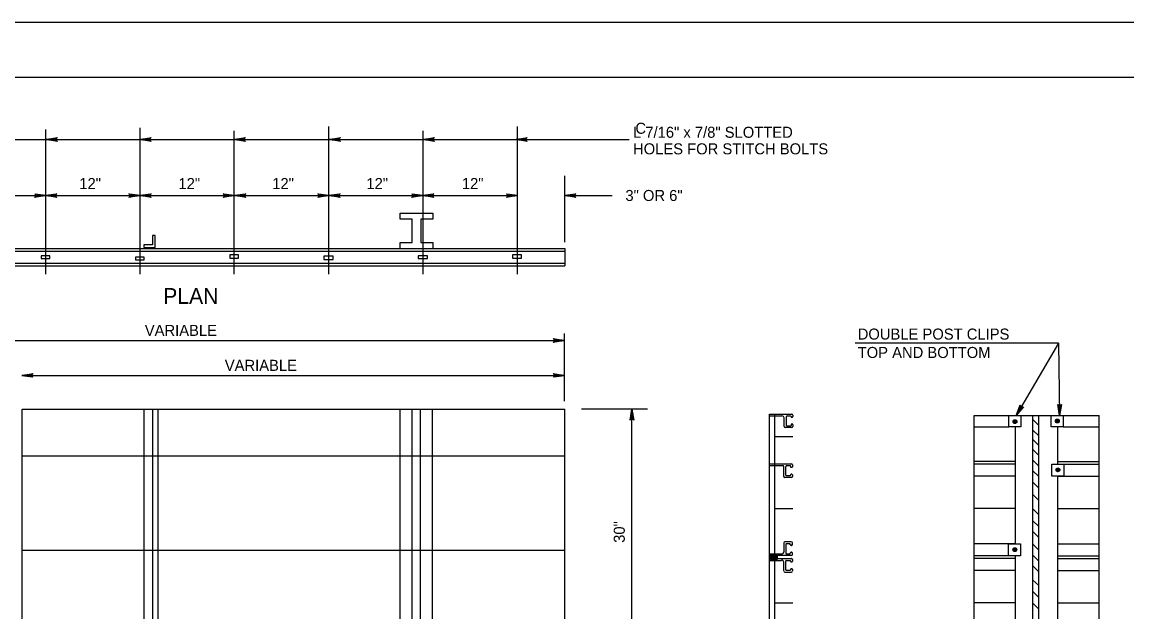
# Model space of a CAD drawing. Extents: x 647822 to 649292, y 298458 to 299646.
# Drawn here: x 647981.4 to 648281.8, y 299485.4 to 299645.6 of the extents above; entities that cross this region are included whole.
import ezdxf

# ---------------------------------------------------------------- set-up
doc = ezdxf.new("R2010")
doc.units = 0
for name, color, linetype in [('1', 7, 'Continuous'), ('2', 7, 'Continuous'), ('3', 7, 'Continuous'), ('XCS-GRID-MIN', 7, 'Continuous')]:
    doc.layers.add(name, color=color, linetype=linetype)

# ---------------------------------------------------------------- blocks, each defined once
blk = doc.blocks.new('RARROW')
at = {"layer": '3'}
blk.add_lwpolyline([(-2.2695, 0.285), (-2.184875, 0.12075), (0, 0), (-2.2695, 0.285), (-2.38575, 0.384625), (0, 0), (-2.183125, -0.108), (-2.262875, -0.2705), (0, 0), (-2.38575, -0.379125), (-2.262875, -0.2705)], dxfattribs=at)

msp = doc.modelspace()

# ---------------------------------------------------------------- linework, layer by layer
at = {"layer": '1'}
msp.add_line((647862.31, 299630.63), (648648.31, 299630.63), dxfattribs=at)
at = {"layer": '2'}
for p, q in [((647987.88, 299577.1), (647987.88, 299616.48)), ((648013.5, 299577.1), (648013.5, 299616.85)), ((648039.13, 299577.1), (648039.13, 299616.1)), ((648064.88, 299577.1), (648064.88, 299617.23)), ((648090.5, 299577.1), (648090.5, 299616.1)), ((648116.13, 299577.1), (648116.13, 299617.23)), ((647962.25, 299613.73), (647987.88, 299613.73)), ((647988, 299613.73), (648013.5, 299613.73)), ((647988, 299613.73), (647988, 299613.73)), ((648013.5, 299613.73), (648039.13, 299613.73)), ((648013.5, 299613.73), (648013.5, 299613.73)), ((648039.13, 299613.73), (648064.88, 299613.73)), ((648039.13, 299613.73), (648039.13, 299613.73)), ((648065, 299613.73), (648090.5, 299613.73)), ((648065, 299613.73), (648065, 299613.73)), ((648090.5, 299613.73), (648115.75, 299613.73)), ((648090.5, 299613.73), (648090.5, 299613.73)), ((648115.75, 299613.73), (648146.5, 299613.73)), ((648115.75, 299613.73), (648115.75, 299613.73)), ((648129, 299585.85), (648129, 299603.85)), ((647962.38, 299598.48), (647987.88, 299598.48)), ((647987.88, 299598.48), (648013.5, 299598.48)), ((648013.5, 299598.48), (648039.13, 299598.48)), ((648039.25, 299598.48), (648064.88, 299598.48)), ((648064.88, 299598.48), (648090.38, 299598.48)), ((648090.38, 299598.48), (648116.13, 299598.48)), ((648129, 299598.48), (648141.88, 299598.48)), ((648084.25, 299592.1), (648084.25, 299593.73)), ((648084.25, 299593.73), (648093.13, 299593.73)), ((648087.5, 299592.1), (648084.25, 299592.1)), ((648087.5, 299585.73), (648087.5, 299592.1)), ((648093.13, 299592.1), (648089.88, 299592.1)), ((648089.88, 299592.1), (648089.88, 299585.73)), ((648093.13, 299593.73), (648093.13, 299592.1)), ((648017.63, 299587.6), (648016.88, 299587.6)), ((648016.88, 299587.6), (648016.88, 299585.1)), ((648017.63, 299584.35), (648017.63, 299587.6)), ((647923.75, 299584.1), (648129, 299584.1)), ((647923.75, 299583.35), (648129, 299583.35)), ((648014.5, 299585.1), (648014.5, 299584.35)), ((648016.88, 299585.1), (648014.5, 299585.1)), ((648014.5, 299584.35), (648017.63, 299584.35)), ((648084.25, 299584.1), (648084.25, 299585.73)), ((648084.25, 299585.73), (648087.5, 299585.73)), ((648089.88, 299585.73), (648093.13, 299585.73)), ((648093.13, 299585.73), (648093.13, 299584.1)), ((648129.13, 299579.35), (648129.13, 299584.1)), ((647923.75, 299580.1), (648129, 299580.1)), ((647989, 299582.1), (647986.63, 299582.1)), ((647986.63, 299582.1), (647986.63, 299581.35)), ((647986.63, 299581.35), (647989, 299581.35)), ((647989, 299581.35), (647989, 299582.1)), ((648014.63, 299581.73), (648012.25, 299581.73)), ((648012.25, 299581.73), (648012.25, 299580.98)), ((648012.25, 299580.98), (648014.63, 299580.98)), ((648014.63, 299580.98), (648014.63, 299581.73)), ((648040.25, 299582.35), (648037.88, 299582.35)), ((648037.88, 299582.35), (648037.88, 299581.48)), ((648037.88, 299581.48), (648040.25, 299581.48)), ((648040.25, 299581.48), (648040.25, 299582.35)), ((648066, 299581.98), (648063.5, 299581.98)), ((648063.5, 299581.98), (648063.5, 299581.1)), ((648063.5, 299581.1), (648066, 299581.1)), ((648066, 299581.1), (648066, 299581.98)), ((648091.63, 299582.1), (648089.13, 299582.1)), ((648089.13, 299582.1), (648089.13, 299581.35)), ((648089.13, 299581.35), (648091.63, 299581.35)), ((648091.63, 299581.35), (648091.63, 299582.1)), ((648117.25, 299582.35), (648114.75, 299582.35)), ((648114.75, 299582.35), (648114.75, 299581.48)), ((648114.75, 299581.48), (648117.25, 299581.48)), ((648117.25, 299581.48), (648117.25, 299582.35)), ((647923.75, 299579.35), (648129, 299579.35)), ((647923.63, 299559.1), (648128.88, 299559.1)), ((648128.88, 299542.6), (648128.88, 299560.98)), ((648263.25, 299558.35), (648207.97, 299558.35)), ((648263.25, 299558.35), (648251.75, 299538.73)), ((648263.25, 299558.35), (648263.5, 299538.73)), ((647981.38, 299549.6), (648128.88, 299549.6)), ((647981.5, 299540.48), (648129, 299540.48)), ((647981.5, 299476.48), (647981.5, 299540.48)), ((648014.5, 299540.48), (648014.5, 299399.48)), ((648016.88, 299540.48), (648016.88, 299399.48)), ((648018.36, 299540.48), (648018.36, 299399.48)), ((648084.25, 299326.41), (648084.25, 299540.48)), ((648087.5, 299326.41), (648087.5, 299540.48)), ((648089.75, 299326.41), (648089.75, 299540.48)), ((648093, 299326.41), (648093, 299540.48)), ((648129, 299335.48), (648129, 299540.48)), ((648151.5, 299540.48), (648133.5, 299540.48)), ((648147.25, 299476.23), (648147.25, 299540.48)), ((648184.63, 299335.43), (648184.63, 299539.1)), ((648184.63, 299539.1), (648190.74, 299539.1)), ((648184.63, 299538.6), (648188, 299538.6)), ((648186.13, 299335.43), (648186.13, 299539.1)), ((648188.63, 299535.74), (648188.63, 299538.1)), ((648189.25, 299536.01), (648189.25, 299538.44)), ((648189.41, 299538.6), (648190.34, 299538.6)), ((648190.5, 299538.44), (648190.5, 299538.39)), ((648190.66, 299538.23), (648190.74, 299538.23)), ((648190.75, 299538.23), (648190.75, 299538.23)), ((648191, 299538.84), (648191, 299538.49)), ((648240.25, 299335.47), (648240.25, 299538.73)), ((648240.25, 299538.73), (648274.25, 299538.73)), ((648249.75, 299535.6), (648249.75, 299538.73)), ((648253, 299538.73), (648253, 299535.6)), ((648256.25, 299335.47), (648256.25, 299538.73)), ((648257.88, 299335.47), (648257.88, 299538.73)), ((648261.25, 299538.73), (648264.5, 299538.73)), ((648261.25, 299535.6), (648261.25, 299538.73)), ((648264.5, 299538.73), (648264.5, 299535.6)), ((648274.25, 299335.47), (648274.25, 299538.73)), ((648190.74, 299535.48), (648188.89, 299535.48)), ((648190.34, 299535.85), (648189.41, 299535.85)), ((648190.5, 299536.21), (648190.5, 299536.01)), ((648190.84, 299536.37), (648190.66, 299536.37)), ((648191, 299536.21), (648191, 299535.74)), ((648240.25, 299535.6), (648249.75, 299535.6)), ((648253, 299535.6), (648249.75, 299535.6)), ((648251.38, 299535.6), (648251.38, 299535.6)), ((648251.5, 299503.85), (648251.5, 299535.6)), ((648257.88, 299535.98), (648256.25, 299537.6)), ((648264.5, 299535.6), (648261.25, 299535.6)), ((648262.88, 299535.6), (648262.88, 299535.6)), ((648263, 299525.48), (648263, 299535.6)), ((648264.5, 299535.6), (648274.25, 299535.6)), ((648186.13, 299532.98), (648191, 299532.98)), ((648257.88, 299533.23), (648256.25, 299534.73)), ((648257.88, 299530.6), (648256.25, 299532.23)), ((648257.88, 299527.85), (648256.25, 299529.48)), ((647981.5, 299527.73), (648129, 299527.73)), ((648251.5, 299526.23), (648240.25, 299526.23)), ((648257.88, 299524.98), (648256.25, 299526.6)), ((648263, 299526.23), (648274.25, 299526.23)), ((648184.63, 299525.6), (648190.62, 299525.6)), ((648184.63, 299525.1), (648188.24, 299525.1)), ((648188.5, 299522.11), (648188.5, 299524.84)), ((648189.13, 299522.51), (648189.13, 299524.84)), ((648189.39, 299525.1), (648190.22, 299525.1)), ((648190.38, 299524.94), (648190.38, 299524.75)), ((648190.72, 299524.59), (648190.54, 299524.59)), ((648190.88, 299525.34), (648190.88, 299524.75)), ((648251.5, 299525.48), (648240.25, 299525.48)), ((648257.88, 299522.1), (648256.25, 299523.73)), ((648261.38, 299525.48), (648264.63, 299525.48)), ((648261.38, 299522.23), (648261.38, 299525.48)), ((648263, 299525.48), (648274.25, 299525.48)), ((648263, 299525.48), (648263, 299525.48)), ((648264.63, 299525.48), (648264.63, 299522.23)), ((648190.62, 299521.85), (648188.76, 299521.85)), ((648190.22, 299522.35), (648189.29, 299522.35)), ((648190.38, 299522.58), (648190.38, 299522.51)), ((648190.72, 299522.74), (648190.54, 299522.74)), ((648190.88, 299522.58), (648190.88, 299522.11)), ((648251.5, 299522.23), (648240.25, 299522.23)), ((648257.88, 299518.98), (648256.25, 299520.6)), ((648264.63, 299522.23), (648261.38, 299522.23)), ((648263, 299522.35), (648263, 299522.35)), ((648263, 299522.23), (648274.25, 299522.23)), ((648263, 299478.85), (648263, 299522.23)), ((648257.88, 299515.6), (648256.25, 299517.23)), ((648186.13, 299513.48), (648191, 299513.48)), ((648251.5, 299513.48), (648240.25, 299513.48)), ((648257.88, 299511.73), (648256.25, 299513.35)), ((648263, 299513.48), (648274.25, 299513.48)), ((648257.88, 299508.6), (648256.25, 299510.1)), ((648257.88, 299505.6), (648256.25, 299507.23)), ((647981.5, 299502.1), (648129, 299502.1)), ((648188.5, 299504.1), (648188.5, 299501.6)), ((648190.5, 299504.35), (648188.88, 299504.35)), ((648189.13, 299503.73), (648189.13, 299501.23)), ((648190.13, 299503.85), (648189.25, 299503.85)), ((648190.25, 299503.6), (648190.25, 299503.73)), ((648190.63, 299503.48), (648190.5, 299503.48)), ((648190.88, 299503.6), (648190.88, 299504.1)), ((648251.5, 299503.85), (648240.25, 299503.85)), ((648249.63, 299503.85), (648252.88, 299503.85)), ((648249.63, 299500.6), (648249.63, 299503.85)), ((648251.25, 299503.85), (648251.25, 299503.85)), ((648252.88, 299503.85), (648252.88, 299500.6)), ((648257.88, 299502.1), (648256.25, 299503.73)), ((648263, 299503.85), (648274.25, 299503.85)), ((648184.63, 299501.1), (648187.88, 299501.1)), ((648184.63, 299500.73), (648190.5, 299500.73)), ((648184.63, 299499.85), (648190.63, 299499.85)), ((648184.63, 299499.35), (648187.88, 299499.35)), ((648188.5, 299496.48), (648188.5, 299498.85)), ((648189.13, 299496.73), (648189.13, 299499.23)), ((648189.25, 299501.1), (648190.13, 299501.1)), ((648189.25, 299499.35), (648190.13, 299499.35)), ((648190.25, 299501.23), (648190.25, 299501.35)), ((648190.38, 299499.23), (648190.38, 299499.1)), ((648190.5, 299501.6), (648190.63, 299501.6)), ((648190.63, 299498.98), (648190.63, 299498.98)), ((648190.88, 299500.98), (648190.88, 299501.35)), ((648190.88, 299499.6), (648190.88, 299499.1)), ((648251.5, 299500.6), (648240.25, 299500.6)), ((648251.5, 299499.85), (648240.25, 299499.85)), ((648252.88, 299500.6), (648249.63, 299500.6)), ((648251.25, 299500.6), (648251.25, 299500.6)), ((648251.5, 299453.1), (648251.5, 299500.6)), ((648257.88, 299499.1), (648256.25, 299500.73)), ((648263, 299500.6), (648274.25, 299500.6)), ((648263, 299499.85), (648274.25, 299499.85)), ((648190.63, 299496.1), (648188.88, 299496.1)), ((648190.13, 299496.6), (648189.25, 299496.6)), ((648190.38, 299496.85), (648190.38, 299496.73)), ((648190.63, 299497.1), (648190.63, 299497.1)), ((648190.88, 299496.85), (648190.88, 299496.48)), ((648251.5, 299496.6), (648240.25, 299496.6)), ((648257.88, 299496.23), (648256.25, 299497.85)), ((648263, 299496.6), (648274.25, 299496.6)), ((648257.88, 299492.48), (648256.25, 299493.98)), ((648257.88, 299489.23), (648256.25, 299490.85)), ((648186.13, 299487.85), (648191, 299487.85)), ((648251.5, 299487.85), (648240.25, 299487.85)), ((648257.88, 299486.1), (648256.25, 299487.73)), ((648263, 299487.85), (648274.25, 299487.85))]:
    msp.add_line(p, q, dxfattribs=at)
for points in [[(648251.25, 299537.48), (648251.13, 299537.23), (648251.13, 299536.85), (648251.38, 299536.73), (648251.63, 299536.85), (648251.75, 299537.1), (648251.75, 299537.35), (648251.63, 299537.48), (648251.38, 299537.48), (648251.25, 299537.23), (648251.25, 299537.1), (648251.25, 299536.98), (648251.38, 299536.98), (648251.5, 299537.1), (648251.63, 299537.23), (648251.5, 299537.35), (648251.5, 299537.23), (648251.38, 299537.1)], [(648262.75, 299537.6), (648262.63, 299537.23), (648262.63, 299536.98), (648262.88, 299536.85), (648263.13, 299536.98), (648263.25, 299537.23), (648263.25, 299537.48), (648263.13, 299537.6), (648262.88, 299537.48), (648262.75, 299537.23), (648262.75, 299537.1), (648262.75, 299537.1), (648262.88, 299536.98), (648263, 299537.23), (648263.13, 299537.23), (648263, 299537.48), (648263, 299537.35), (648262.88, 299537.1)], [(648262.88, 299524.35), (648262.75, 299523.98), (648262.75, 299523.73), (648263, 299523.48), (648263.25, 299523.6), (648263.38, 299523.85), (648263.38, 299524.1), (648263.25, 299524.35), (648263.13, 299524.23), (648262.88, 299523.98), (648262.88, 299523.85), (648262.88, 299523.73), (648263, 299523.73), (648263.13, 299523.85), (648263.25, 299523.98), (648263.25, 299524.1), (648263.13, 299523.98), (648263, 299523.85)], [(648251.25, 299502.6), (648251, 299502.35), (648251, 299501.98), (648251.25, 299501.85), (648251.5, 299501.98), (648251.63, 299502.23), (648251.63, 299502.48), (648251.5, 299502.6), (648251.38, 299502.6), (648251.13, 299502.35), (648251.13, 299502.23), (648251.13, 299502.1), (648251.38, 299502.1), (648251.5, 299502.23), (648251.5, 299502.35), (648251.5, 299502.48), (648251.38, 299502.35), (648251.25, 299502.23)], [(648186.75, 299500.98), (648186.75, 299499.6), (648184.88, 299499.6), (648184.75, 299500.98), (648186.25, 299500.73), (648186.38, 299500.85), (648186.38, 299499.85), (648185.13, 299499.85), (648185.13, 299500.48), (648185.88, 299500.6), (648186, 299500.1), (648185.38, 299500.1), (648185.38, 299500.98), (648186.25, 299500.98), (648186.25, 299500.73)]]:
    msp.add_lwpolyline(points, dxfattribs=at)
for centre in [(648251.38, 299537.06), (648262.91, 299537.23), (648263.06, 299523.97), (648251.34, 299502.26)]:
    msp.add_circle(centre, 0.525, dxfattribs=at)
for centre, radius, start, end in [((648189.41, 299538.44), 0.16, 90, 180), ((648190.34, 299538.44), 0.16, 0, 90), ((648190.66, 299538.39), 0.16, 180, 270), ((648190.74, 299538.84), 0.26, 0, 90), ((648190.74, 299538.49), 0.26, 270, 0), ((648188.89, 299535.74), 0.26, 180, 270), ((648189.41, 299536.01), 0.16, 180, 270), ((648190.34, 299536.01), 0.16, 270, 0), ((648190.66, 299536.21), 0.16, 90, 180), ((648190.74, 299535.74), 0.26, 270, 0), ((648190.84, 299536.21), 0.16, 0, 90), ((648188.24, 299524.84), 0.26, 0, 90), ((648189.39, 299524.84), 0.26, 90, 180), ((648190.22, 299524.94), 0.16, 0, 90), ((648190.54, 299524.75), 0.16, 180, 270), ((648190.62, 299525.34), 0.26, 0, 90), ((648190.72, 299524.75), 0.16, 270, 0), ((648188.76, 299522.11), 0.26, 180, 270), ((648189.29, 299522.51), 0.16, 180, 270), ((648190.22, 299522.51), 0.16, 270, 0), ((648190.54, 299522.58), 0.16, 90, 180), ((648190.62, 299522.11), 0.26, 270, 0), ((648190.72, 299522.58), 0.16, 0, 90)]:
    msp.add_arc(centre, radius, start, end, dxfattribs=at)
for centre, major_axis, start_param, end_param in [((648187.98, 299538.08), (0.653, 0), 0, 1.570796), ((648188.84, 299504.09), (-0.327, 0), 4.712389, 6.283185), ((648189.25, 299503.76), (-0.163, 0), 4.712389, 6.283185), ((648190.14, 299503.76), (-0.163, 0), 3.141593, 4.712389), ((648190.56, 299503.64), (0.251, 0), 3.141593, 4.712389), ((648190.56, 299504.09), (0.327, 0), 0, 1.570796), ((648190.63, 299503.64), (0.251, 0), 4.712389, 6.283185), ((648187.86, 299501.65), (0.653, 0), 4.712389, 6.283185), ((648187.88, 299498.88), (0.653, 0), 0, 1.570796), ((648189.25, 299501.25), (0.163, 0), 3.141593, 4.712389), ((648189.27, 299499.27), (-0.163, 0), 4.712389, 6.283185), ((648190.14, 299501.25), (0.163, 0), 4.712389, 6.283185), ((648190.17, 299499.27), (0.163, 0), 0, 1.570796), ((648190.56, 299501.39), (-0.251, 0), 4.712389, 6.283185), ((648190.58, 299499.14), (-0.251, 0), 0, 1.570796), ((648190.56, 299500.93), (0.327, 0), 4.712389, 6.283185), ((648190.58, 299499.6), (0.327, 0), 0, 1.570796), ((648190.63, 299501.39), (0.251, 0), 0, 1.570796), ((648190.66, 299499.14), (0.251, 0), 4.712389, 6.283185), ((648188.86, 299496.43), (0.327, 0), 3.141593, 4.712389), ((648189.27, 299496.76), (-0.163, 0), 0, 1.570796), ((648190.17, 299496.76), (0.163, 0), 4.712389, 6.283185), ((648190.58, 299496.89), (-0.251, 0), 4.712389, 6.283185), ((648190.58, 299496.43), (0.327, 0), 4.712389, 6.283185), ((648190.66, 299496.89), (-0.251, 0), 3.141593, 4.712389)]:
    msp.add_ellipse(centre, major_axis=major_axis, ratio=0.806863, start_param=start_param, end_param=end_param, dxfattribs=at)
at = {"layer": 'XCS-GRID-MIN'}
msp.add_lwpolyline([(647822.31, 299645.63), (648663.31, 299645.63), (648663.31, 299051.63), (647822.31, 299051.63)], close=True, dxfattribs=at)

# ---------------------------------------------------------------- block references
at = {"layer": '2', "xscale": 1.2574347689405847, "yscale": 1.3092961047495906}
for p, rotation in [((647988, 299613.73), 180), ((648013.5, 299613.73), 180), ((648039.13, 299613.73), 180), ((648065, 299613.73), 180), ((648090.5, 299613.73), 180), ((648115.75, 299613.73), 180), ((647987.88, 299598.48), 180), ((648013.5, 299598.48), 180), ((648039.25, 299598.48), 180), ((648064.88, 299598.48), 180), ((648090.38, 299598.48), 180), ((648129, 299598.48), 180), ((647981.38, 299549.6), 180), ((648251.75, 299538.73), -119.77918658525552), ((648263.5, 299538.73), -90.00000000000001), ((648147.25, 299540.48), 89.99999999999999)]:
    msp.add_blockref('RARROW', p, dxfattribs=dict(at, rotation=rotation))
for p in [(647987.88, 299598.48), (648013.5, 299598.48), (648039.13, 299598.48), (648064.88, 299598.48), (648090.38, 299598.48), (648116.13, 299598.48), (648128.88, 299559.1), (648128.88, 299549.6)]:
    msp.add_blockref('RARROW', p, dxfattribs=at)

# ---------------------------------------------------------------- texts
at = {"layer": '2'}
for s, height, p in [(' L 7/16" x 7/8" SLOTTED', 3, (648146.43, 299614.19)), ('C', 3, (648148.19, 299615.28)), (' HOLES FOR STITCH BOLTS', 3, (648146.43, 299609.69)), ('12"', 3, (647997, 299600.26)), ('12"', 3, (648023.95, 299600.26)), ('12"', 3, (648049.45, 299600.26)), ('12"', 3, (648075.05, 299600.26)), ('12"', 3, (648101, 299600.26)), ('3" OR 6"', 3, (648145.47, 299597.01)), ('PLAN', 4.3, (648019.8, 299569.05)), ('VARIABLE', 3, (648014.8, 299560.35)), ('DOUBLE POST CLIPS', 3, (648208.63, 299559.35)), ('TOP AND BOTTOM', 3, (648208.63, 299554.35)), ('VARIABLE', 3, (648036.55, 299550.85))]:
    msp.add_text(s, height=height, dxfattribs=at).set_placement(p)
msp.add_text('30"', height=3, rotation=90, dxfattribs=at).set_placement((648145.3, 299504.11))

doc.saveas('drawing.dxf')
